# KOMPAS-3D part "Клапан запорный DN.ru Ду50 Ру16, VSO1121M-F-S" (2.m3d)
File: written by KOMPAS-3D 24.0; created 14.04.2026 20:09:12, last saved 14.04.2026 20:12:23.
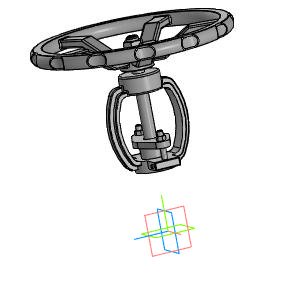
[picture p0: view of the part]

Document properties: Автор: R2D2; Полное имя файла: E:\Работа\Зайцев\VSO3131M-F-S Клапан запорный DN.ru Ду15-100 Ру40\DN50\исходные материалы\2.m3d

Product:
- Part/product: Клапан запорный DN.ru Ду50 Ру16  | designation VSO1121M-F-S
    Масса: 14.13
    Раздел спецификации: Прочие изделия
    Примечание: D090-01947

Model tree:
1. Операция без истории:1
2. Эскиз:1  (with: Грань.Операция без истории:1)
3. Элемент вращения:1
     Угол 1 = 360
4. Эскиз:2  (with: Грань.Операция без истории:1, Ребро.Операция без истории:1)
5. Элемент выдавливания:1  (with: Грань.Операция без истории:1)
     Расстояние 1 = -90
6. Эскиз:3  (with: Грань.Операция без истории:1, Ребро.Элемент выдавливания:1, Вершина.Операция без истории:1, Ребро.Операция без истории:1)
7. Элемент выдавливания:2  (with: Грань.Элемент выдавливания:1)
     Расстояние 1 = -34.0167; Смещение 1 = 2; Расстояние 2 = -2
8. Фаска:1  (with: Грань.Элемент выдавливания:1)
     Угол = 45; Длина 1 = 1; Длина 2 = 1

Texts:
  VSO1121M-F-S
